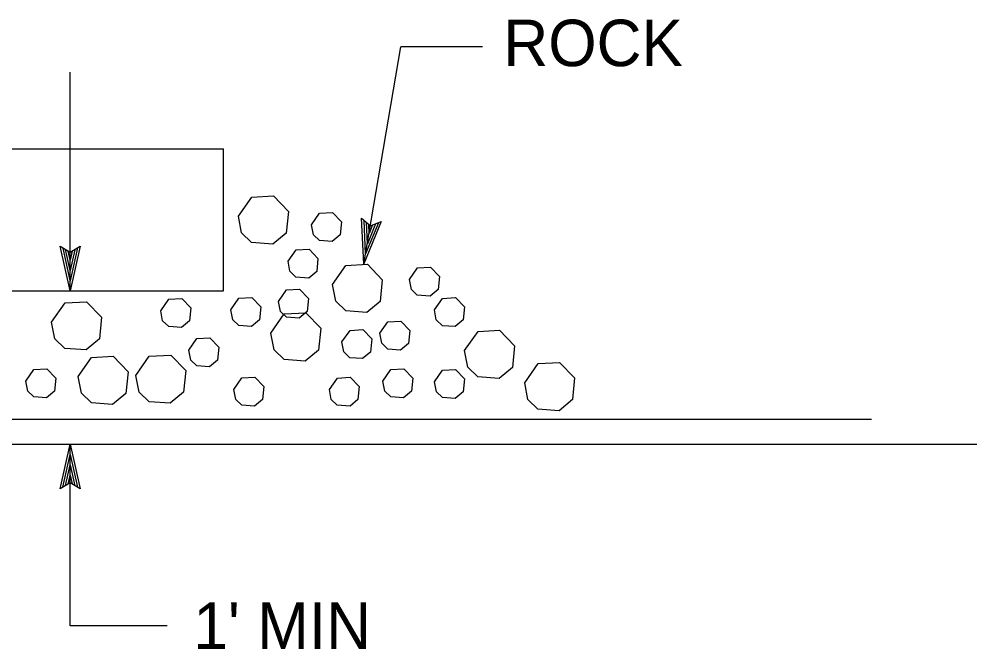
# Model space of a CAD drawing. Extents: x 6709491 to 6710959, y 1869789 to 1870763.
# Drawn here: x 6709920.9 to 6710043.7, y 1869817.7 to 1869899 of the extents above; entities that cross this region are included whole.
import ezdxf

# ---------------------------------------------------------------- set-up
doc = ezdxf.new("R2010")
doc.units = 0
for name, color, linetype in [('56 Stg 3 Anno', 7, 'Continuous'), ('57 Undefined', 7, 'Continuous'), ('60 Nongeo Data', 7, 'Continuous')]:
    doc.layers.add(name, color=color, linetype=linetype)

msp = doc.modelspace()

# ---------------------------------------------------------------- linework, layer by layer
at = {"layer": '56 Stg 3 Anno'}
for p, q in [((6709965.46, 1869867.42), (6709970.22, 1869895.44)), ((6709980.76, 1869895.44), (6709970.22, 1869895.44)), ((6709927.54, 1869863.92), (6709927.54, 1869892.18)), ((6709965.46, 1869867.42), (6709965.16, 1869873.31)), ((6709965.16, 1869873.31), (6709965.16, 1869873.31)), ((6709965.16, 1869873.31), (6709966.29, 1869872.34)), ((6709967.69, 1869872.88), (6709965.46, 1869867.42)), ((6709965.68, 1869868.73), (6709965.47, 1869873.03)), ((6709967.32, 1869872.73), (6709965.68, 1869868.72)), ((6709965.9, 1869870.03), (6709965.77, 1869872.81)), ((6709966.94, 1869872.57), (6709965.9, 1869870.03)), ((6709966.13, 1869871.34), (6709966.07, 1869872.53)), ((6709966.29, 1869872.34), (6709967.69, 1869872.88)), ((6709967.69, 1869872.88), (6709967.69, 1869872.88)), ((6709966.58, 1869872.46), (6709966.13, 1869871.34)), ((6709927.54, 1869863.92), (6709926.26, 1869869.69)), ((6709926.26, 1869869.69), (6709926.26, 1869869.69)), ((6709926.26, 1869869.69), (6709927.54, 1869868.92)), ((6709927.54, 1869865.26), (6709926.61, 1869869.46)), ((6709927.54, 1869866.58), (6709926.94, 1869869.29)), ((6709927.54, 1869867.9), (6709927.29, 1869869.06)), ((6709927.54, 1869868.92), (6709928.83, 1869869.69)), ((6709928.83, 1869869.69), (6709927.54, 1869863.92)), ((6709928.49, 1869869.48), (6709927.54, 1869865.25)), ((6709928.14, 1869869.25), (6709927.54, 1869866.58)), ((6709927.81, 1869869.08), (6709927.54, 1869867.9)), ((6709928.83, 1869869.69), (6709928.83, 1869869.69)), ((6709965.46, 1869867.42), (6709965.46, 1869867.42)), ((6709927.54, 1869863.92), (6709927.54, 1869863.92)), ((6709926.25, 1869838.38), (6709927.54, 1869844.14)), ((6709927.54, 1869820.7), (6709927.54, 1869844.14)), ((6709927.54, 1869844.14), (6709927.54, 1869844.14)), ((6709927.54, 1869844.14), (6709928.82, 1869838.38)), ((6709926.6, 1869838.59), (6709927.54, 1869842.82)), ((6709927.54, 1869842.8), (6709928.47, 1869838.61)), ((6709926.94, 1869838.81), (6709927.54, 1869841.49)), ((6709927.54, 1869841.49), (6709928.14, 1869838.78)), ((6709927.27, 1869838.98), (6709927.54, 1869840.16)), ((6709927.54, 1869840.16), (6709927.8, 1869839)), ((6709927.54, 1869839.15), (6709926.25, 1869838.38)), ((6709926.25, 1869838.38), (6709926.25, 1869838.38)), ((6709928.82, 1869838.38), (6709927.54, 1869839.15)), ((6709928.82, 1869838.38), (6709928.82, 1869838.38)), ((6709940.07, 1869820.7), (6709927.54, 1869820.7))]:
    msp.add_line(p, q, dxfattribs=at)
at = {"layer": '60 Nongeo Data'}
for p, q in [((6709602.72, 1869882.28), (6709947.32, 1869882.28)), ((6709947.32, 1869863.92), (6709947.32, 1869882.28)), ((6709756.24, 1869863.92), (6709947.32, 1869863.92)), ((6709755.52, 1869847.39), (6710030.98, 1869847.39)), ((6709754.44, 1869844.14), (6710047.92, 1869844.14))]:
    msp.add_line(p, q, dxfattribs=at)
for points in [[(6709949.25, 1869873.57), (6709950.99, 1869876.05), (6709953.77, 1869876.21), (6709955.7, 1869874.2), (6709955.42, 1869871.4), (6709953.7, 1869869.97), (6709950.96, 1869870.17), (6709949.67, 1869871.42), (6709949.25, 1869873.57)], [(6709958.68, 1869872.47), (6709959.72, 1869873.96), (6709961.39, 1869874.05), (6709962.55, 1869872.85), (6709962.38, 1869871.17), (6709961.35, 1869870.31), (6709959.7, 1869870.43), (6709958.93, 1869871.18), (6709958.68, 1869872.47)], [(6709955.66, 1869867.75), (6709956.7, 1869869.23), (6709958.37, 1869869.33), (6709959.52, 1869868.13), (6709959.36, 1869866.45), (6709958.33, 1869865.59), (6709956.68, 1869865.71), (6709955.91, 1869866.46), (6709955.66, 1869867.75)], [(6709961.39, 1869864.75), (6709963.13, 1869867.23), (6709965.9, 1869867.39), (6709967.83, 1869865.38), (6709967.55, 1869862.58), (6709965.84, 1869861.15), (6709963.1, 1869861.35), (6709961.81, 1869862.6), (6709961.39, 1869864.75)], [(6709971.33, 1869865.41), (6709972.37, 1869866.9), (6709974.04, 1869866.99), (6709975.2, 1869865.79), (6709975.03, 1869864.11), (6709974, 1869863.25), (6709972.35, 1869863.37), (6709971.58, 1869864.12), (6709971.33, 1869865.41)], [(6709954.43, 1869862.56), (6709955.47, 1869864.05), (6709957.14, 1869864.14), (6709958.3, 1869862.94), (6709958.13, 1869861.26), (6709957.1, 1869860.4), (6709955.46, 1869860.52), (6709954.68, 1869861.27), (6709954.43, 1869862.56)], [(6709939.22, 1869861.36), (6709940.27, 1869862.85), (6709941.93, 1869862.94), (6709943.09, 1869861.74), (6709942.92, 1869860.06), (6709941.89, 1869859.2), (6709940.25, 1869859.32), (6709939.47, 1869860.07), (6709939.22, 1869861.36)], [(6709948.26, 1869861.49), (6709949.3, 1869862.98), (6709950.97, 1869863.07), (6709952.13, 1869861.87), (6709951.96, 1869860.19), (6709950.93, 1869859.33), (6709949.29, 1869859.45), (6709948.51, 1869860.2), (6709948.26, 1869861.49)], [(6709974.55, 1869861.48), (6709975.6, 1869862.97), (6709977.26, 1869863.06), (6709978.42, 1869861.86), (6709978.25, 1869860.18), (6709977.22, 1869859.32), (6709975.58, 1869859.44), (6709974.8, 1869860.19), (6709974.55, 1869861.48)], [(6709925.13, 1869859.91), (6709926.87, 1869862.38), (6709929.65, 1869862.54), (6709931.58, 1869860.54), (6709931.3, 1869857.74), (6709929.58, 1869856.31), (6709926.84, 1869856.51), (6709925.55, 1869857.76), (6709925.13, 1869859.91)], [(6709953.43, 1869858.47), (6709955.17, 1869860.95), (6709957.95, 1869861.1), (6709959.88, 1869859.1), (6709959.6, 1869856.3), (6709957.88, 1869854.87), (6709955.14, 1869855.07), (6709953.85, 1869856.32), (6709953.43, 1869858.47)], [(6709967.51, 1869858.46), (6709968.55, 1869859.94), (6709970.22, 1869860.04), (6709971.37, 1869858.84), (6709971.21, 1869857.16), (6709970.18, 1869856.3), (6709968.53, 1869856.42), (6709967.76, 1869857.17), (6709967.51, 1869858.46)], [(6709942.85, 1869856.28), (6709943.89, 1869857.77), (6709945.56, 1869857.86), (6709946.72, 1869856.66), (6709946.55, 1869854.98), (6709945.52, 1869854.12), (6709943.87, 1869854.24), (6709943.1, 1869854.99), (6709942.85, 1869856.28)], [(6709962.62, 1869857.35), (6709963.67, 1869858.83), (6709965.33, 1869858.93), (6709966.49, 1869857.73), (6709966.32, 1869856.04), (6709965.29, 1869855.19), (6709963.65, 1869855.31), (6709962.87, 1869856.06), (6709962.62, 1869857.35)], [(6709978.45, 1869856.23), (6709980.19, 1869858.7), (6709982.97, 1869858.86), (6709984.9, 1869856.86), (6709984.62, 1869854.05), (6709982.9, 1869852.63), (6709980.16, 1869852.83), (6709978.87, 1869854.08), (6709978.45, 1869856.23)], [(6709928.56, 1869852.86), (6709930.3, 1869855.34), (6709933.08, 1869855.49), (6709935.01, 1869853.49), (6709934.73, 1869850.69), (6709933.01, 1869849.26), (6709930.27, 1869849.46), (6709928.98, 1869850.71), (6709928.56, 1869852.86)], [(6709936, 1869853.02), (6709937.74, 1869855.49), (6709940.52, 1869855.65), (6709942.45, 1869853.65), (6709942.17, 1869850.85), (6709940.45, 1869849.42), (6709937.71, 1869849.62), (6709936.42, 1869850.87), (6709936, 1869853.02)], [(6709986.21, 1869852.06), (6709987.95, 1869854.54), (6709990.72, 1869854.7), (6709992.65, 1869852.7), (6709992.37, 1869849.89), (6709990.66, 1869848.46), (6709987.92, 1869848.66), (6709986.63, 1869849.91), (6709986.21, 1869852.06)], [(6709921.8, 1869852.28), (6709922.85, 1869853.77), (6709924.51, 1869853.86), (6709925.67, 1869852.66), (6709925.5, 1869850.98), (6709924.47, 1869850.12), (6709922.83, 1869850.24), (6709922.05, 1869850.99), (6709921.8, 1869852.28)], [(6709967.89, 1869852.29), (6709968.93, 1869853.78), (6709970.6, 1869853.87), (6709971.76, 1869852.67), (6709971.59, 1869850.99), (6709970.56, 1869850.13), (6709968.91, 1869850.25), (6709968.14, 1869851), (6709967.89, 1869852.29)], [(6709974.57, 1869852.21), (6709975.62, 1869853.7), (6709977.28, 1869853.79), (6709978.44, 1869852.59), (6709978.27, 1869850.91), (6709977.24, 1869850.05), (6709975.6, 1869850.17), (6709974.83, 1869850.92), (6709974.57, 1869852.21)], [(6709948.65, 1869851.2), (6709949.69, 1869852.69), (6709951.36, 1869852.78), (6709952.52, 1869851.58), (6709952.35, 1869849.9), (6709951.32, 1869849.04), (6709949.68, 1869849.16), (6709948.9, 1869849.91), (6709948.65, 1869851.2)], [(6709960.99, 1869851.2), (6709962.03, 1869852.68), (6709963.7, 1869852.78), (6709964.86, 1869851.58), (6709964.69, 1869849.89), (6709963.66, 1869849.04), (6709962.01, 1869849.16), (6709961.24, 1869849.91), (6709960.99, 1869851.2)]]:
    msp.add_lwpolyline(points, dxfattribs=at)

# ---------------------------------------------------------------- texts
at = {"layer": '57 Undefined'}
for s, p in [('ROCK', (6709983.46, 1869892.95)), ("1' MIN", (6709943.44, 1869817.7))]:
    msp.add_text(s, height=6, dxfattribs=at).set_placement(p)

doc.saveas('drawing.dxf')
